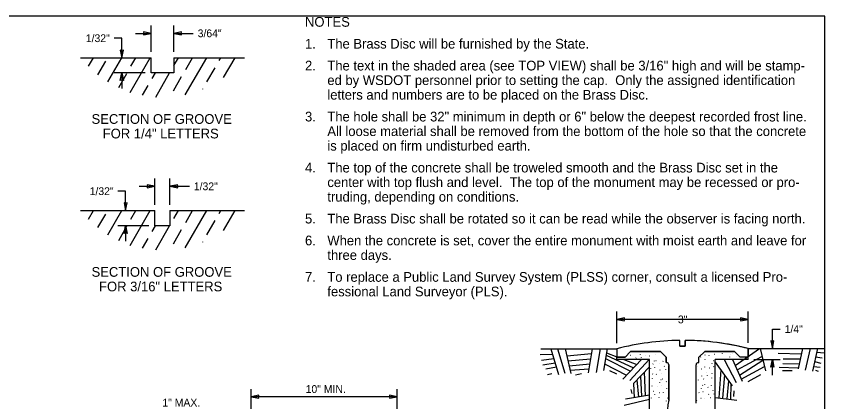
# Model space of a CAD drawing. Extents: x 99862 to 103151, y 100000 to 102076.
# Drawn here: x 101489 to 103151, y 101282 to 102076 of the extents above; entities that cross this region are included whole.
import ezdxf

# ---------------------------------------------------------------- set-up
doc = ezdxf.new("R2010")
doc.units = 0
for name, color, linetype in [('Level 1', 7, 'Continuous'), ('Level 11', 7, 'Continuous'), ('Level 15', 7, 'Continuous'), ('Level 17', 7, 'Continuous'), ('Level 20', 7, 'Continuous'), ('Level 21', 7, 'Continuous'), ('Level 26', 7, 'Continuous'), ('Level 28', 7, 'Continuous'), ('Level 6', 7, 'Continuous'), ('Level 60', 7, 'Continuous'), ('Level 7', 7, 'Continuous')]:
    doc.layers.add(name, color=color, linetype=linetype)

msp = doc.modelspace()

# ---------------------------------------------------------------- linework, layer by layer
at = {"layer": 'Level 1'}
msp.add_lwpolyline([(99862, 99999.5), (103151, 99999.5), (103151, 102075.5), (99862, 102075.5)], close=True, dxfattribs=at)
at = {"layer": 'Level 11'}
for p, q in [((102723.4, 101368.8), (102723.4, 101373.6)), ((102993.4, 101368.8), (102993.4, 101374.3)), ((102790.8, 101368.8), (102723.4, 101368.8)), ((102790.8, 101081.2), (102790.8, 101368.8)), ((102993.4, 101368.8), (102925.8, 101368.8)), ((102925.8, 101081.2), (102925.8, 101368.8))]:
    msp.add_line(p, q, dxfattribs=at)
at = {"layer": 'Level 15'}
for p, q in [((101766.1, 102002), (101766.1, 102056)), ((101813, 102002), (101813, 102056)), ((101734.1, 102040), (101766.1, 102040)), ((101813, 102040), (101853, 102040)), ((101706.1, 102030), (101690.1, 102030)), ((101706.1, 101990), (101706.1, 102030)), ((101754.1, 101958.8), (101690.1, 101958.8)), ((101706.1, 101958.8), (101706.1, 101926.8)), ((101773.9, 101687.2), (101773.9, 101741.2)), ((101805.1, 101687.2), (101805.1, 101741.2)), ((101741.9, 101725.2), (101773.9, 101725.2)), ((101805.1, 101725.2), (101845.1, 101725.2)), ((101713.9, 101715.2), (101697.9, 101715.2)), ((101713.9, 101675.2), (101713.9, 101715.2)), ((101761.9, 101644), (101697.9, 101644)), ((101713.9, 101644), (101713.9, 101612)), ((102723.3, 101402.5), (102723.3, 101467.3)), ((102993.4, 101403.2), (102993.4, 101467.3)), ((102993.4, 101451.2), (102723.3, 101451.2)), ((103043.4, 101391.3), (103043.4, 101431.3)), ((103043.4, 101431.3), (103059.4, 101431.3)), ((103005.4, 101391.3), (103059.4, 101391.3)), ((103005.4, 101368.8), (103059.4, 101368.8)), ((103043.4, 101336.8), (103043.4, 101368.8)), ((101972.2, 101223.9), (101972.2, 101307.9)), ((102272.2, 101223.9), (102272.2, 101307.9)), ((102272.2, 101291.9), (101972.2, 101291.9))]:
    msp.add_line(p, q, dxfattribs=at)
for points in [[(101766.1, 102040), (101750.4, 102043.1), (101751.1, 102040), (101750.4, 102037)], [(101813, 102040), (101828.7, 102037), (101828, 102040), (101828.7, 102043.1)], [(101706.1, 101990), (101709.2, 102005.8), (101706.1, 102005), (101703, 102005.8)], [(101706.1, 101958.8), (101709.2, 101943.1), (101706.1, 101943.8), (101703, 101943.1)], [(101773.9, 101725.2), (101758.2, 101728.3), (101758.9, 101725.2), (101758.2, 101722.1)], [(101805.1, 101725.2), (101820.9, 101722.1), (101820.1, 101725.2), (101820.9, 101728.3)], [(101713.9, 101675.2), (101717, 101690.9), (101713.9, 101690.2), (101710.8, 101690.9)], [(101713.9, 101644), (101717, 101628.2), (101713.9, 101629), (101710.8, 101628.2)], [(102723.3, 101451.2), (102739.1, 101448.2), (102738.3, 101451.2), (102739.1, 101454.3)], [(102993.4, 101451.2), (102977.7, 101454.3), (102978.4, 101451.2), (102977.7, 101448.2)], [(103043.4, 101391.3), (103046.5, 101407), (103043.4, 101406.3), (103040.3, 101407)], [(103043.4, 101368.8), (103046.5, 101353), (103043.4, 101353.8), (103040.3, 101353)], [(101972.2, 101291.9), (101987.9, 101288.8), (101987.2, 101291.9), (101987.9, 101295)], [(102272.2, 101291.9), (102256.4, 101295), (102257.2, 101291.9), (102256.4, 101288.8)]]:
    msp.add_lwpolyline(points, close=True, dxfattribs=at)
for start, end in [(110.2589, 110.2681), (110.2589, 110.2681), (70.3048, 70.3116), (70.3048, 70.3116)]:
    msp.add_arc((102858.4, 101392.3), 16.5, start, end, dxfattribs=at)
at = {"layer": 'Level 17'}
for p, q in [((102567.3, 101390.5), (102723.4, 101390.5)), ((102993.4, 101391.3), (103149.5, 101391.3))]:
    msp.add_line(p, q, dxfattribs=at)
at = {"layer": 'Level 26'}
for p, q in [((102725.3, 101373.2), (102725.7, 101372.9)), ((102742.6, 101375.5), (102743, 101375.2)), ((102750.9, 101377.7), (102751.3, 101377.4)), ((102762.8, 101371.5), (102762.9, 101372.2)), ((102771.2, 101379.7), (102771.6, 101379.3)), ((102774.1, 101372.4), (102774.2, 101373.1)), ((102783, 101377.2), (102783.4, 101376.8)), ((102790.8, 101376.6), (102791.1, 101376)), ((102798.8, 101384.5), (102798.8, 101384.9)), ((102802, 101378.6), (102802.5, 101378.3)), ((102895.8, 101373.7), (102895.9, 101374.4)), ((102904.7, 101378.4), (102905.1, 101378.1)), ((102912.5, 101377.8), (102912.8, 101377.2)), ((102923.8, 101379.9), (102924.2, 101379.6)), ((102940.8, 101381.1), (102940.8, 101381.8)), ((102955.5, 101373.5), (102955.5, 101374.2)), ((102957.7, 101380), (102958.1, 101379.7)), ((102961.6, 101381.2), (102962, 101380.9)), ((102968.7, 101375.7), (102969.1, 101375.4)), ((102797.8, 101359.2), (102797.9, 101359.9)), ((102800, 101365.7), (102800.4, 101365.4)), ((102800.6, 101352.7), (102801.1, 101352.4)), ((102803.9, 101366.9), (102804.3, 101366.6)), ((102811.1, 101361.4), (102811.5, 101361)), ((102818.3, 101364.9), (102818.4, 101365.6)), ((102821, 101354.7), (102821.4, 101354.4)), ((102889.7, 101355), (102890.1, 101354.7)), ((102904.1, 101353), (102904.1, 101353.7)), ((102904.8, 101368.1), (102904.9, 101368.8)), ((102919.5, 101360.4), (102919.6, 101361.1)), ((102921.7, 101366.9), (102922.1, 101366.6)), ((102922.4, 101354), (102922.8, 101353.7)), ((102925.6, 101368.1), (102925.8, 101368)), ((102978.7, 101369), (102979, 101368.8)), ((102792.4, 101350.6), (102792.8, 101350.3)), ((102796.8, 101339.1), (102797.3, 101338.8)), ((102804.6, 101338.5), (102804.9, 101338)), ((102812.6, 101346.5), (102812.7, 101347.2)), ((102815.9, 101340.6), (102816.3, 101340.3)), ((102823.9, 101347.5), (102824, 101348.2)), ((102886.5, 101340.8), (102886.8, 101340.6)), ((102896.8, 101349.5), (102897.2, 101349.2)), ((102906.8, 101342.9), (102907.2, 101342.5)), ((102909.7, 101335.6), (102909.7, 101336.3)), ((102914.1, 101351.8), (102914.5, 101351.5)), ((102918.6, 101340.4), (102919, 101340)), ((102797, 101328.8), (102797, 101329.5)), ((102811.7, 101321.2), (102811.7, 101321.9)), ((102813.8, 101327.6), (102814.3, 101327.3)), ((102817.7, 101328.9), (102818.2, 101328.6)), ((102824.9, 101323.3), (102825.3, 101323)), ((102890.4, 101326.7), (102890.7, 101326.1)), ((102898.4, 101334.7), (102898.4, 101335.4)), ((102901.6, 101328.8), (102902.1, 101328.4)), ((102918.7, 101330), (102918.7, 101330.7)), ((102796.2, 101313.8), (102796.3, 101314.5)), ((102798.9, 101303.6), (102799.3, 101303.3)), ((102806.2, 101312.5), (102806.7, 101312.2)), ((102814.5, 101314.7), (102814.9, 101314.4)), ((102826.5, 101308.5), (102826.5, 101309.2)), ((102897.4, 101309.3), (102897.5, 101310)), ((102899.6, 101315.8), (102900, 101315.5)), ((102900.2, 101302.8), (102900.7, 101302.5)), ((102903.5, 101317), (102903.9, 101316.7)), ((102910.6, 101311.5), (102911.1, 101311.2)), ((102917.9, 101315), (102918, 101315.7)), ((102920.6, 101304.8), (102921, 101304.5)), ((102793.8, 101289.5), (102794.2, 101289.2)), ((102801.8, 101296.4), (102801.8, 101297.1)), ((102810.7, 101301.1), (102811.1, 101300.8)), ((102810.8, 101290.8), (102810.8, 101291.5)), ((102818.5, 101300.5), (102818.8, 101299.9)), ((102827.7, 101289.6), (102828.1, 101289.3)), ((102829.7, 101302.6), (102830.1, 101302.3)), ((102892, 101300.7), (102892.4, 101300.4)), ((102896.4, 101289.2), (102896.9, 101288.9)), ((102904.2, 101288.7), (102904.5, 101288.1)), ((102912.2, 101296.6), (102912.3, 101297.3)), ((102915.5, 101290.7), (102915.9, 101290.4)), ((102923.5, 101297.6), (102923.5, 101298.3)), ((102825.5, 101283.1), (102825.6, 101283.8)), ((102887.5, 101284.5), (102887.6, 101285.2))]:
    msp.add_line(p, q, dxfattribs=at)
at = {"layer": 'Level 28'}
for p, q in [((102587.7, 101390.5), (102603.8, 101337.6)), ((102601.3, 101390.5), (102616.3, 101340.7)), ((102617.5, 101390.5), (102628.8, 101339.9)), ((102672.8, 101390.5), (102664.6, 101341.5)), ((102689.3, 101390.5), (102681, 101342.2)), ((102703.8, 101390.5), (102695.8, 101346.1)), ((102966.5, 101356.7), (103016.9, 101391.3)), ((103017.8, 101391.3), (103028.9, 101345.4)), ((103104.9, 101391.3), (103096, 101349.3)), ((103120.9, 101391.3), (103110.8, 101347)), ((103135.9, 101391.3), (103125.6, 101344.6)), ((102591.2, 101379), (102566.2, 101378)), ((102594, 101370), (102569, 101366.9)), ((102620.6, 101376.4), (102671.2, 101380.8)), ((102623, 101365.7), (102669.4, 101370.2)), ((102700.2, 101370.7), (102751.5, 101344.9)), ((102701.5, 101377.7), (102757.6, 101351.3)), ((102702.4, 101382.5), (102723.4, 101374.4)), ((102970.8, 101347.1), (103021.7, 101375)), ((103055.4, 101381.8), (103102.6, 101380.5)), ((103065.7, 101370.4), (103100.4, 101369.9)), ((103132.1, 101373.9), (103145.8, 101371.8)), ((103134.1, 101383.5), (103150, 101382.2)), ((102596.7, 101361.1), (102571.2, 101357)), ((102625.3, 101355.6), (102667.7, 101360.1)), ((102698.3, 101359.8), (102743.1, 101336.3)), ((102774.5, 101368.8), (102735.6, 101328.5)), ((102737.9, 101368.8), (102764.6, 101358.5)), ((102790.2, 101368.8), (102750.5, 101325.4)), ((102790.8, 101353.8), (102757.5, 101319.1)), ((102925.8, 101363.5), (102960.3, 101314.4)), ((102944.1, 101368.8), (102968.9, 101321.5)), ((102961, 101368.8), (102981.3, 101323.8)), ((102975.5, 101336.8), (103023.7, 101367.1)), ((102979.3, 101328.3), (103026.8, 101354.3)), ((103057.3, 101352.9), (103096.5, 101351.6)), ((103065, 101360.5), (103098.2, 101359.5)), ((103127.7, 101354), (103141.4, 101353)), ((103130, 101364.5), (103142.5, 101361.5)), ((102599.2, 101352.7), (102577.8, 101348.7)), ((102581.3, 101338), (102590.1, 101339.7)), ((102627.3, 101346.6), (102666, 101349.8)), ((102638.7, 101337.1), (102651, 101339.7)), ((102708.3, 101346), (102723, 101339.3)), ((102779.9, 101342.4), (102781.9, 101293.7)), ((102937.4, 101347.1), (102932.9, 101289.9)), ((102944.5, 101337), (102940.7, 101288.8)), ((102993.3, 101323.7), (103019.8, 101337.8)), ((103064.3, 101346.4), (103084.1, 101346.4)), ((103131.8, 101346.8), (103137.1, 101344.6)), ((102764.9, 101326.8), (102767.9, 101291.5)), ((102771.9, 101334.2), (102774.3, 101292.5)), ((102952.9, 101324.9), (102949.7, 101287.6)), ((102752.5, 101307), (102754.2, 101299)), ((102757.5, 101319.1), (102759, 101290)), ((102957.7, 101318.1), (102957.1, 101286.6)), ((102964.2, 101303.9), (102963.3, 101292.4)), ((102790.8, 101286.7), (102738.8, 101273.9)), ((102790.8, 101295.2), (102741.1, 101287.1)), ((102925.8, 101290.8), (102970.4, 101284.8))]:
    msp.add_line(p, q, dxfattribs=at)
at = {"layer": 'Level 6'}
for p, q in [((101621.1, 101990), (101766.1, 101990)), ((101766.1, 101958.8), (101766.1, 101990)), ((101813, 101990), (101813, 101958.8)), ((101813, 101990), (101958, 101990)), ((101813, 101958.8), (101766.1, 101958.8)), ((101621.1, 101675.2), (101773.9, 101675.2)), ((101773.9, 101644), (101773.9, 101675.2)), ((101805.1, 101675.2), (101805.1, 101644)), ((101805.1, 101675.2), (101958, 101675.2)), ((101805.1, 101644), (101773.9, 101644)), ((102852.8, 101396), (102852.8, 101408)), ((102852.8, 101396), (102852.8, 101408)), ((102852.8, 101396), (102852.8, 101408)), ((102864.1, 101396), (102864.1, 101408)), ((102864.1, 101396), (102864.1, 101408)), ((102864.1, 101408), (102864.1, 101396)), ((102723.4, 101390.5), (102723.4, 101373.6)), ((102723.4, 101390.5), (102723.4, 101373.6)), ((102723.4, 101390.5), (102723.4, 101373.6)), ((102852.8, 101396), (102864.1, 101396)), ((102852.8, 101396), (102864.1, 101396)), ((102864.1, 101396), (102852.8, 101396)), ((102993.4, 101391.3), (102993.4, 101374.3)), ((102993.4, 101391.3), (102993.4, 101374.3)), ((102993.4, 101374.3), (102993.4, 101391.2)), ((102740.3, 101373.6), (102723.4, 101373.6)), ((102740.3, 101373.6), (102723.4, 101373.6)), ((102723.4, 101373.6), (102740.3, 101373.6)), ((102751.5, 101384.9), (102740.3, 101373.6)), ((102751.5, 101384.9), (102740.3, 101373.6)), ((102740.3, 101373.6), (102751.5, 101384.9)), ((102813.3, 101384.9), (102751.5, 101384.9)), ((102813.3, 101384.9), (102751.5, 101384.9)), ((102751.5, 101384.9), (102813.3, 101384.9)), ((102813.3, 101384.9), (102824.6, 101373.6)), ((102813.3, 101384.9), (102824.6, 101373.6)), ((102813.3, 101384.9), (102824.6, 101373.6)), ((102824.6, 101362.4), (102824.6, 101373.6)), ((102824.6, 101373.6), (102824.6, 101362.4)), ((102904.1, 101384.9), (102892.1, 101373.6)), ((102904.1, 101384.9), (102892.1, 101373.6)), ((102892.1, 101373.6), (102904.1, 101384.9)), ((102892.1, 101362.4), (102892.1, 101373.6)), ((102892.1, 101362.4), (102892.1, 101373.6)), ((102965.2, 101384.9), (102904.1, 101384.9)), ((102965.2, 101384.9), (102904.1, 101384.9)), ((102904.1, 101384.9), (102965.2, 101384.9)), ((102965.2, 101384.9), (102976.6, 101374.3)), ((102965.2, 101384.9), (102976.6, 101374.3)), ((102965.2, 101384.9), (102976.6, 101374.3)), ((102976.6, 101374.3), (102993.4, 101374.3)), ((102976.6, 101374.3), (102993.4, 101374.3)), ((102976.6, 101374.3), (102993.4, 101374.3)), ((102825.7, 101362.4), (102824.6, 101362.4)), ((102824.6, 101362.4), (102825.7, 101362.4)), ((102830.3, 101357.9), (102830.3, 101356.8)), ((102830.3, 101357.9), (102830.3, 101356.8)), ((102830.3, 101294.9), (102830.3, 101356.7)), ((102830.3, 101356.7), (102830.3, 101294.9)), ((102886.5, 101294.9), (102886.5, 101357.9)), ((102886.5, 101294.9), (102886.5, 101357.9)), ((102892.1, 101362.4), (102891, 101362.4)), ((102892.1, 101362.4), (102891, 101362.4)), ((102891, 101362.4), (102892.1, 101362.4)), ((102830.3, 101284.8), (102830.3, 101294.9)), ((102830.3, 101294.9), (102830.3, 101284.8)), ((102886.5, 101279.1), (102886.5, 101294.9)), ((102886.5, 101279.1), (102886.5, 101294.9))]:
    msp.add_line(p, q, dxfattribs=at)
for centre, radius, start, end in [((102859.8, 100867.9), 540.2, 90.7461, 104.6317), ((102859.8, 100867.9), 540.2, 90.7461, 104.6317), ((102859.8, 100867.9), 540.2, 90.7461, 104.6237), ((102859.8, 100867.9), 540.2, 75.6765, 89.5524), ((102859.8, 100867.9), 540.2, 81.5269, 89.5465), ((102859.8, 100867.9), 540.2, 75.6765, 81.5269), ((102859.8, 100867.9), 540.2, 75.6769, 81.5268), ((102825.7, 101357.9), 4.5, 0, 90), ((102825.7, 101357.9), 4.5, 0.1464, 90), ((102891, 101357.9), 4.5, 90, 180), ((102891, 101357.9), 4.5, 90.2096, 180), ((103129.9, 101229.7), 304.7, 169.5778, 198.8057), ((103129.9, 101229.7), 304.7, 169.5778, 198.8057)]:
    msp.add_arc(centre, radius, start, end, dxfattribs=at)
at = {"layer": 'Level 60'}
msp.add_line((103151, 102075.5), (103151, 102075.5), dxfattribs=at)
at = {"layer": 'Level 7'}
for p, q in [((101637.7, 101972.5), (101647.9, 101990)), ((101677.3, 101940.2), (101706.1, 101990)), ((101723, 101918.5), (101764.3, 101990)), ((101724.9, 101972.3), (101735.2, 101990)), ((101813, 101973.6), (101822.5, 101990)), ((101836.5, 101913.5), (101880.7, 101990)), ((101837.4, 101965.5), (101851.6, 101990)), ((101906.3, 101984), (101909.8, 101990)), ((101915.1, 101948.9), (101938.9, 101990)), ((101656.7, 101954.9), (101672.9, 101982.9)), ((101881.1, 101940.3), (101897.9, 101969.4)), ((101699.7, 101928.6), (101716.5, 101957.7)), ((101768.6, 101947.1), (101775.3, 101958.8)), ((101775.7, 101909), (101804.4, 101958.8)), ((101812.2, 101921.9), (101829, 101951)), ((101748.6, 101912.5), (101760.2, 101932.5)), ((101872.4, 101925.3), (101872.7, 101925.8)), ((101637.7, 101657.7), (101647.9, 101675.2)), ((101677.3, 101625.4), (101706.1, 101675.2)), ((101723, 101603.7), (101764.3, 101675.2)), ((101724.9, 101657.5), (101735.2, 101675.2)), ((101813, 101658.8), (101822.5, 101675.2)), ((101836.5, 101598.7), (101880.7, 101675.2)), ((101837.4, 101650.7), (101851.6, 101675.2)), ((101906.3, 101669.2), (101909.8, 101675.2)), ((101915.1, 101634.1), (101938.9, 101675.2)), ((101656.7, 101640.1), (101672.9, 101668.1)), ((101881.1, 101625.5), (101897.9, 101654.6)), ((101699.7, 101613.8), (101716.5, 101642.9)), ((101768.6, 101632.3), (101775.3, 101644)), ((101775.7, 101594.2), (101804.4, 101644)), ((101812.2, 101607.1), (101829, 101636.2)), ((101748.6, 101597.7), (101760.2, 101617.7)), ((101872.4, 101610.5), (101872.7, 101611))]:
    msp.add_line(p, q, dxfattribs=at)

# ---------------------------------------------------------------- texts
at = {"layer": 'Level 20'}
for s, height, p in [('NOTES', 20, (102082.6, 102053.7)), ('1/32"', 16, (101632.1, 102022.1)), ('3/64"', 16, (101862, 102032.1)), ('1.', 20, (102082.6, 102008.7)), ('The Brass Disc will be furnished by the State.', 20, (102128.5, 102008.7)), ('The text in the shaded area (see TOP VIEW) shall be 3/16" high and will be stamp-', 20, (102128.5, 101963.7)), ('2.', 20, (102082.6, 101963.7)), ('ed by WSDOT personnel prior to setting the cap.  Only the assigned identification ', 20, (102128.5, 101933.7)), ('letters and numbers are to be placed on the Brass Disc.', 20, (102128.5, 101903.7)), ('3.', 20, (102082.6, 101858.7)), ('The hole shall be 32" minimum in depth or 6" below the deepest recorded frost line.  ', 20, (102128.5, 101858.7)), ('All loose material shall be removed from the bottom of the hole so that the concrete ', 20, (102128.5, 101828.7)), ('is placed on firm undisturbed earth.', 20, (102128.5, 101798.7)), ('4.', 20, (102082.6, 101753.7)), ('The top of the concrete shall be troweled smooth and the Brass Disc set in the ', 20, (102128.5, 101753.7)), ('center with top flush and level.  The top of the monument may be recessed or pro-', 20, (102128.5, 101723.7)), ('1/32"', 16, (101640, 101707.2)), ('1/32"', 16, (101854.1, 101717.2)), ('truding, depending on conditions.', 20, (102128.5, 101693.7)), ('5.', 20, (102082.6, 101648.7)), ('The Brass Disc shall be rotated so it can be read while the observer is facing north.', 20, (102128.5, 101648.7)), ('6.', 20, (102082.6, 101603.7)), ('When the concrete is set, cover the entire monument with moist earth and leave for ', 20, (102128.5, 101603.7)), ('three days.', 20, (102128.5, 101573.7)), ('7.', 20, (102082.6, 101528.7)), ('To replace a Public Land Survey System (PLSS) corner, consult a licensed Pro-', 20, (102128.5, 101528.7)), ('fessional Land Surveyor (PLS).', 20, (102128.5, 101498.7)), ('3"', 16, (102849, 101443.2)), ('1/4"', 16, (103068.4, 101423.3)), ('10" MIN.', 16, (102083.9, 101299.9)), ('1" MAX.', 16, (101789.4, 101271.9))]:
    msp.add_text(s, height=height, dxfattribs=at).set_placement(p)
at = {"layer": 'Level 21'}
for s, p in [('SECTION OF GROOVE', (101643.9, 101853.8)), ('FOR 1/4" LETTERS', (101666.9, 101823.8)), ('SECTION OF GROOVE', (101643.9, 101539)), ('FOR 3/16" LETTERS', (101659.3, 101509))]:
    msp.add_text(s, height=20, dxfattribs=at).set_placement(p)

doc.saveas('drawing.dxf')
